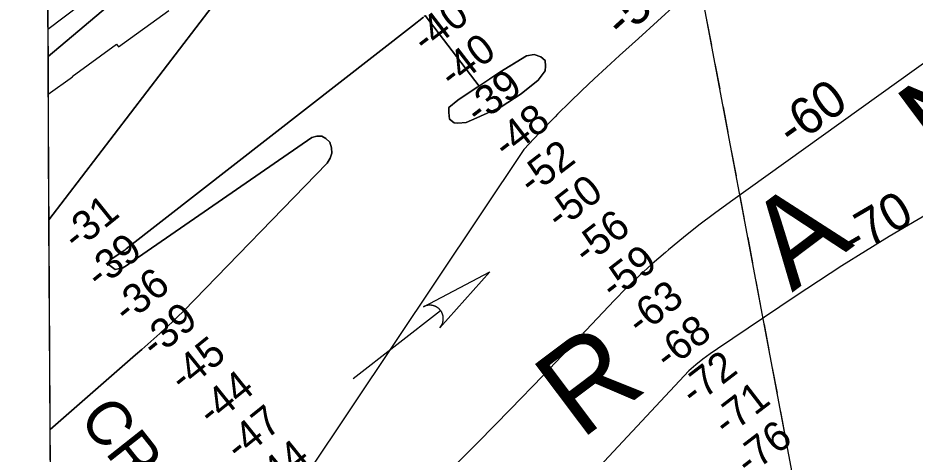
# Model space of a CAD drawing. Extents: x 3477039 to 3515015, y 546746 to 572297.
# Drawn here: x 3481169 to 3483194, y 557076 to 558060 of the extents above; entities that cross this region are included whole.
import ezdxf

# ---------------------------------------------------------------- set-up
doc = ezdxf.new("R2010")
doc.units = 0
for name, color, linetype in [('V-GRID-FRAM', 7, 'Continuous'), ('V-RIVR-FERY', 7, 'Continuous'), ('V-RIVR-IDEN', 7, 'Continuous'), ('V-RIVR-RANG', 7, 'Continuous'), ('V-RRAP-RVMT', 7, 'Continuous'), ('V-STRM-FLOW', 7, 'Continuous'), ('V-TOPO-DPTH', 7, 'Continuous'), ('V-TOPO-GNAM-IDEN', 7, 'Continuous'), ('V-TOPO-MAJR', 7, 'Continuous'), ('V-TOPO-MAJR-IDEN', 7, 'Continuous'), ('V-TOPO-MINR', 7, 'Continuous'), ('V-TOPO-MINR-IDEN', 7, 'Continuous')]:
    doc.layers.add(name, color=color, linetype=linetype)

msp = doc.modelspace()

# ---------------------------------------------------------------- linework, layer by layer
at = {"layer": 'V-GRID-FRAM'}
msp.add_lwpolyline([(3481168.5, 570290.2), (3512800, 570478.9), (3512916.4, 552296.1), (3481269, 552107.3), (3481168.5, 570290.2)], dxfattribs=at)
at = {"layer": 'V-RIVR-FERY'}
for points in [[(3483030.9, 556427.9), (3482556.2, 558946.5)], [(3482734.8, 557998.7), (3482724, 558055.9)], [(3482753.4, 557900.5), (3482742.6, 557957.8)], [(3482771.9, 557802.3), (3482761.1, 557859.6)], [(3482790.4, 557704.1), (3482779.6, 557761.4)], [(3482808.9, 557606), (3482798.1, 557663.3)], [(3482827.4, 557507.8), (3482816.6, 557565.1)], [(3482845.9, 557409.6), (3482835.1, 557466.9)], [(3482864.4, 557311.5), (3482853.6, 557368.7)], [(3482882.9, 557213.3), (3482872.1, 557270.6)], [(3482901.4, 557115.1), (3482890.6, 557172.4)]]:
    msp.add_lwpolyline(points, dxfattribs=at)
at = {"layer": 'V-RRAP-RVMT'}
for p, q in [((3481235.5, 558165.3), (3481237.1, 557888.1)), ((3481395.7, 557995.2), (3481508.8, 558077.5)), ((3481290.8, 557928.5), (3481391.1, 558001.4)), ((3481391.1, 558001.4), (3481395.7, 557995.2)), ((3481237.1, 557888.1), (3481291.5, 557927.7)), ((3481291.5, 557927.7), (3481290.8, 557928.5))]:
    msp.add_line(p, q, dxfattribs=at)
at = {"layer": 'V-STRM-FLOW'}
msp.add_line((3481924.9, 557246.2), (3482122.3, 557400.4), dxfattribs=at)
msp.add_lwpolyline([(3482084.1, 557408.6), (3482233.9, 557487.5), (3482121, 557361.3), (3482122.9, 557363.7), (3482124.5, 557366.2), (3482125.1, 557367.2), (3482125.6, 557368.1), (3482126.1, 557369.3), (3482126.6, 557370.4), (3482127, 557371.4), (3482127.4, 557372.8), (3482127.8, 557374.3), (3482128, 557375.1), (3482128.3, 557376.2), (3482128.5, 557377.7), (3482128.6, 557378.8), (3482128.7, 557380), (3482128.7, 557380.8), (3482128.7, 557381.7), (3482128.7, 557382.8), (3482128.7, 557383.8), (3482128.6, 557384.8), (3482128.5, 557385.6), (3482128.3, 557386.8), (3482128.1, 557388), (3482127.8, 557388.9), (3482127.6, 557390), (3482127.3, 557390.9), (3482127, 557391.7), (3482126.8, 557392.3), (3482126.4, 557393.2), (3482126, 557394.2), (3482125.6, 557395.1), (3482125.1, 557396), (3482124.7, 557396.8), (3482124.2, 557397.6), (3482123.7, 557398.3), (3482123.1, 557399.3), (3482122.3, 557400.4), (3482122, 557400.7), (3482121.6, 557401.2), (3482121.1, 557401.7), (3482120.7, 557402.3), (3482120.2, 557402.8), (3482119.7, 557403.2), (3482119.1, 557403.8), (3482118.7, 557404.2), (3482118.1, 557404.7), (3482117.6, 557405.2), (3482117.1, 557405.5), (3482116.1, 557406.3), (3482115.5, 557406.7), (3482115.1, 557407), (3482114.4, 557407.5), (3482113.8, 557407.8), (3482113.1, 557408.2), (3482112.3, 557408.6), (3482111.6, 557409), (3482111, 557409.3), (3482110.5, 557409.5), (3482109.8, 557409.8), (3482109.1, 557410.1), (3482108.4, 557410.3), (3482107.6, 557410.6), (3482106.8, 557410.8), (3482105.8, 557411.1), (3482105.1, 557411.3), (3482104.3, 557411.5), (3482103.5, 557411.6), (3482102.9, 557411.7), (3482102.2, 557411.8), (3482101.2, 557411.9), (3482101.1, 557411.9), (3482100.5, 557412), (3482100, 557412), (3482099.3, 557412.1), (3482098.5, 557412.1), (3482097.8, 557412.1), (3482097.2, 557412.1), (3482096.4, 557412), (3482095.6, 557412), (3482095.1, 557411.9), (3482094.4, 557411.8), (3482093.4, 557411.7), (3482092.9, 557411.6), (3482092.4, 557411.5), (3482092, 557411.4), (3482091.5, 557411.3), (3482090.9, 557411.2), (3482090.3, 557411), (3482089.6, 557410.8), (3482089, 557410.7), (3482088.2, 557410.4), (3482087.8, 557410.2), (3482087, 557409.9), (3482086.2, 557409.6), (3482085.5, 557409.3), (3482085.1, 557409.1), (3482084.6, 557408.9), (3482084.3, 557408.7)], close=True, dxfattribs=at)
at = {"layer": 'V-TOPO-DPTH'}
for p, q in [((3481238.6, 557604.5), (3481236.6, 557973.1)), ((3481241.2, 557131.5), (3481238.6, 557604.5))]:
    msp.add_line(p, q, dxfattribs=at)
for points in [[(3481828.4, 558376.2), (3481238.6, 557604.5)], [(3481238.6, 557604.5), (3481828.4, 558376.2)], [(3481236.6, 557973.1), (3481562.1, 558248.2)], [(3481236.6, 557973.1), (3481562.1, 558248.2)], [(3482083.8, 558062.4), (3482059, 558042.6), (3481413.1, 557539), (3481410, 557536.6), (3481378.8, 557515.8), (3481375.8, 557513.4), (3481371.2, 557504.6), (3481374.9, 557502.5), (3481378.8, 557499.2), (3481387.9, 557492.7), (3481394.5, 557494), (3481405.6, 557496.5), (3481412.8, 557501.1), (3481418, 557505), (3481428.5, 557512.2), (3481832, 557790.3), (3481843.6, 557793.7), (3481854.3, 557793.7), (3481863.7, 557788.6), (3481872.3, 557780), (3481876.3, 557767.5), (3481877.2, 557755.4), (3481873.3, 557743.9), (3481866.3, 557732.8), (3481541.9, 557398.9), (3481529, 557385.9), (3481515.9, 557373.1), (3481502.6, 557360.6), (3481489, 557348.2), (3481475.4, 557336.1), (3481461.7, 557323.9), (3481447.9, 557311.8), (3481434.1, 557299.7), (3481241.2, 557131.5)], [(3481241.2, 557131.5), (3481434.1, 557299.7), (3481447.9, 557311.8), (3481461.7, 557323.9), (3481475.4, 557336.1), (3481489, 557348.2), (3481502.6, 557360.6), (3481515.9, 557373.1), (3481529, 557385.9), (3481541.9, 557398.9), (3481866.3, 557732.8), (3481873.3, 557743.9), (3481877.2, 557755.4), (3481876.3, 557767.5), (3481872.3, 557780), (3481863.7, 557788.6), (3481854.3, 557793.7), (3481843.6, 557793.7), (3481832, 557790.3), (3481428.5, 557512.2), (3481418, 557505), (3481412.8, 557501.1), (3481405.6, 557496.5), (3481394.5, 557494), (3481387.9, 557492.7), (3481378.8, 557499.2), (3481374.9, 557502.5), (3481371.2, 557504.6), (3481375.8, 557513.4), (3481378.8, 557515.8), (3481410, 557536.6), (3481413.1, 557539), (3482059, 558042.6), (3482083.8, 558062.4)], [(3482085.8, 558064.1), (3482088.1, 558066), (3482209.6, 557906.8), (3482205.5, 557904), (3482161.9, 557875.1), (3482141.2, 557858.6), (3482141.1, 557847), (3482142.7, 557832), (3482153.5, 557823.7), (3482161.8, 557822.9), (3482180, 557824.5), (3482204.1, 557835.2), (3482259.7, 557860), (3482304.6, 557888.9), (3482342.8, 557920.3), (3482358.6, 557941), (3482359.5, 557951.8), (3482358.7, 557964.2), (3482348.7, 557972.5), (3482333.8, 557977.6), (3482316.4, 557975.1), (3482256.6, 557937.9), (3482209.6, 557906.8), (3482088.1, 558066)], [(3482277.1, 557950.7), (3482316.4, 557975.1), (3482333.8, 557977.6), (3482348.7, 557972.5), (3482358.7, 557964.2), (3482359.5, 557951.8), (3482358.6, 557941), (3482342.8, 557920.3), (3482304.6, 557888.9), (3482259.7, 557860), (3482204.1, 557835.2), (3482180, 557824.5), (3482161.8, 557822.9), (3482153.5, 557823.7), (3482142.7, 557832), (3482141.1, 557847), (3482141.2, 557858.6), (3482161.9, 557875.1), (3482256.6, 557937.9), (3482274.6, 557949.1), (3482277.1, 557950.7)], [(3481253.5, 554907.7), (3481241.2, 557131.5)]]:
    msp.add_lwpolyline(points, dxfattribs=at)
at = {"layer": 'V-TOPO-MAJR'}
msp.add_lwpolyline([(3482655.5, 558092.3), (3482612.6, 558053.3), (3482569.7, 558014.4), (3482526.7, 557975.4), (3482497.4, 557948.8), (3482469.3, 557922.9), (3482441.4, 557896.8), (3482414, 557870.2), (3482386.8, 557843.3), (3482381, 557837.4), (3482357.1, 557813.1), (3482333.6, 557788.4), (3482310.6, 557763.4), (3481822.2, 557032.8), (3481802.6, 557015.1), (3481782.5, 556998), (3481762.1, 556981.3), (3481244.4, 556569.1)], dxfattribs=at)
at = {"layer": 'V-TOPO-MINR'}
for points in [[(3481792.2, 558454.7), (3481236.3, 558034.2)], [(3481828.4, 558376.2), (3481238.6, 557604.5)], [(3481562.1, 558248.2), (3481236.6, 557973.1)], [(3482083.8, 558062.4), (3482059, 558042.6), (3481413.1, 557539), (3481410, 557536.6), (3481378.8, 557515.8), (3481375.8, 557513.4), (3481371.2, 557504.6), (3481374.9, 557502.5), (3481378.8, 557499.2), (3481387.9, 557492.7), (3481394.5, 557494), (3481405.6, 557496.5), (3481412.8, 557501.1), (3481418, 557505), (3481428.5, 557512.2), (3481832, 557790.3), (3481843.6, 557793.7), (3481854.3, 557793.7), (3481863.7, 557788.6), (3481872.3, 557780), (3481876.3, 557767.5), (3481877.2, 557755.4), (3481873.3, 557743.9), (3481866.3, 557732.8), (3481541.9, 557398.9), (3481529, 557385.9), (3481515.9, 557373.1), (3481502.6, 557360.6), (3481489, 557348.2), (3481475.4, 557336.1), (3481461.7, 557323.9), (3481447.9, 557311.8), (3481434.1, 557299.7), (3481241.2, 557131.5)], [(3483361.4, 558064.1), (3482776.7, 557645), (3482741.1, 557618.9), (3482705.8, 557592.3), (3482671.2, 557564.8), (3482637, 557536.9), (3482630, 557531), (3482600, 557505.1), (3482570.7, 557478.6), (3482542.4, 557451), (3482514.7, 557422.7), (3482425.4, 557328.4), (3482353.2, 557252.8), (3482280.6, 557177.6), (3482207.3, 557103), (3482133.5, 557028.9)], [(3483244.2, 557630.9), (3483135.5, 557567.4), (3483028.7, 557500.6), (3482923.2, 557431.7), (3482747.8, 557313.6), (3482731.2, 557301.9), (3482714.8, 557289.9), (3482698.8, 557277.2), (3482683.2, 557264.2), (3482258.2, 556808.4)]]:
    msp.add_lwpolyline(points, dxfattribs=at)
msp.add_lwpolyline([(3482161.9, 557875.1), (3482256.6, 557937.9), (3482316.4, 557975.1), (3482333.8, 557977.6), (3482348.7, 557972.5), (3482358.7, 557964.2), (3482359.5, 557951.8), (3482358.6, 557941), (3482342.8, 557920.3), (3482304.6, 557888.9), (3482259.7, 557860), (3482204.1, 557835.2), (3482180, 557824.5), (3482161.8, 557822.9), (3482153.5, 557823.7), (3482142.7, 557832), (3482141.1, 557847), (3482141.2, 557858.6)], close=True, dxfattribs=at)

# ---------------------------------------------------------------- texts
at = {"layer": 'V-RIVR-IDEN'}
for s, rotation, p in [('N', 36.7718, (3483257.8, 557717)), ('A', 36.9743, (3482916.1, 557440.1)), ('R', 36.9743, (3482438.5, 557106.2))]:
    msp.add_text(s, height=200, rotation=rotation, dxfattribs=at).set_placement(p)
at = {"layer": 'V-RIVR-RANG'}
for s, rotation, p in [('-40', 37.5543, (3482088.9, 557977.9)), ('-40', 37.5543, (3482149.7, 557898.5)), ('-39', 37.5543, (3482208.4, 557817.5)), ('-48', 37.5543, (3482271.4, 557739.8)), ('-52', 37.5543, (3482328.8, 557657.8)), ('-50', 37.5543, (3482391, 557579.5)), ('-31', 38.8341, (3481300.8, 557533)), ('-56', 37.5543, (3482452.4, 557500.6)), ('-39', 38.8341, (3481352.6, 557446.4)), ('-59', 37.5543, (3482513.4, 557421.3)), ('-36', 38.8341, (3481414.9, 557368.2)), ('-63', 37.5543, (3482573.1, 557341.1)), ('-39', 38.8341, (3481477.7, 557290.3)), ('-68', 37.5543, (3482635.9, 557263.3)), ('-45', 38.8341, (3481541.6, 557213.4)), ('-72', 37.5543, (3482694.6, 557182.2)), ('-44', 38.8341, (3481605.6, 557136.5)), ('-71', 37.5543, (3482768.5, 557112.9)), ('-47', 38.8341, (3481667.7, 557058.1)), ('-76', 37.5543, (3482818.2, 557025)), ('-44', 38.8341, (3481730.6, 556980.4))]:
    msp.add_text(s, height=67, rotation=rotation, dxfattribs=at).set_placement(p)
at = {"layer": 'V-TOPO-GNAM-IDEN'}
msp.add_text('CRESCENT LDG.', height=100, rotation=308.3535, dxfattribs=at).set_placement((3481303.7, 557154.5))
at = {"layer": 'V-TOPO-MAJR-IDEN'}
msp.add_text('-50', height=83, rotation=42.2583, dxfattribs=at).set_placement((3482533.6, 558011))
at = {"layer": 'V-TOPO-MINR-IDEN'}
for s, rotation, p in [('-60', 35.626, (3482916.9, 557766.7)), ('-70', 30.3222, (3483057.5, 557521.7))]:
    msp.add_text(s, height=83, rotation=rotation, dxfattribs=at).set_placement(p)

doc.saveas('drawing.dxf')
